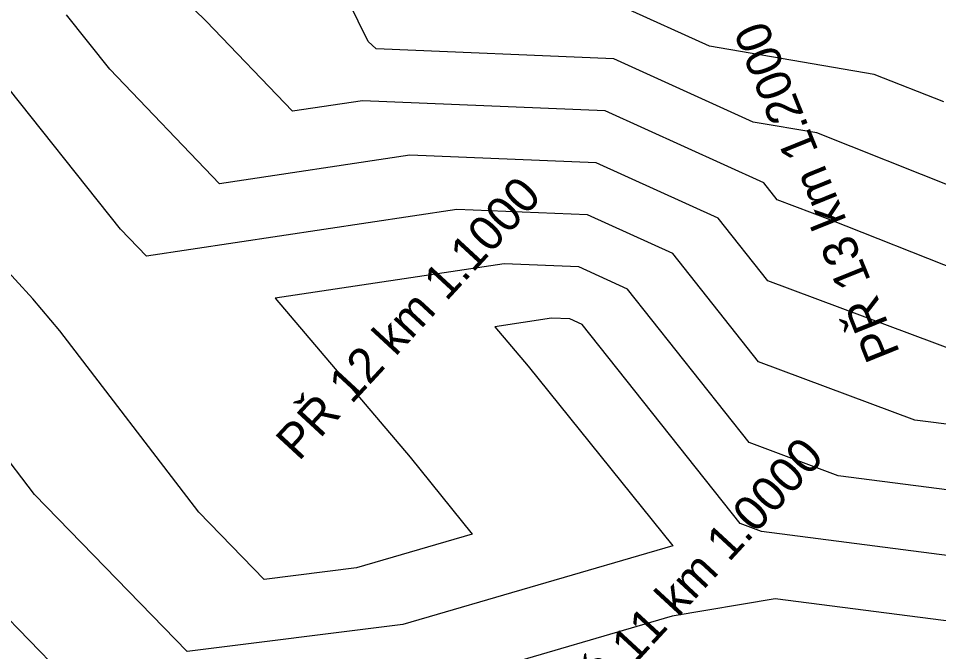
# Model space of a CAD drawing. Extents: x -549394 to -546608, y -1037055 to -1033629.
# Drawn here: x -548577.2 to -548337.9, y -1034297.2 to -1034132.6 of the extents above; entities that cross this region are included whole.
import ezdxf

# ---------------------------------------------------------------- set-up
doc = ezdxf.new("R2010")
doc.units = 0
for name, color, linetype in [('hlavni_vrst', 7, 'Continuous'), ('norm_vrst', 7, 'Continuous'), ('x_popis_pricne_rezy_C21', 7, 'Continuous')]:
    doc.layers.add(name, color=color, linetype=linetype)

msp = doc.modelspace()

# ---------------------------------------------------------------- linework, layer by layer
at = {"layer": 'hlavni_vrst'}
for p, q in [((-548550.64, -1034187.34), (-548582.87, -1034146.92)), ((-548463.15, -1034182.22), (-548543.89, -1034194.39)), ((-548429.21, -1034183.63), (-548463.15, -1034182.22)), ((-548407, -1034193.71), (-548429.21, -1034183.63)), ((-548543.89, -1034194.39), (-548550.64, -1034187.34)), ((-548384.72, -1034221.8), (-548407, -1034193.71)), ((-548344.1, -1034237.02), (-548384.72, -1034221.8)), ((-548328.37, -1034239.03), (-548344.1, -1034237.02))]:
    msp.add_line(p, q, dxfattribs=at)
at = {"layer": 'norm_vrst'}
for p, q in [((-548528.34, -1034133.25), (-548548.15, -1034114.12)), ((-548486.29, -1034138.6), (-548491.42, -1034127.98)), ((-548397.49, -1034139.82), (-548420.1, -1034129.55)), ((-548553.4, -1034145.77), (-548564.7, -1034131.6)), ((-548505.89, -1034156.71), (-548528.34, -1034133.25)), ((-548484.16, -1034140.51), (-548486.29, -1034138.6)), ((-548354.65, -1034147.1), (-548397.49, -1034139.82)), ((-548422.38, -1034143.07), (-548484.16, -1034140.51)), ((-548386.15, -1034159.52), (-548422.38, -1034143.07)), ((-548524.89, -1034175.55), (-548553.4, -1034145.77)), ((-548336.57, -1034154.28), (-548354.65, -1034147.1)), ((-548487.74, -1034153.97), (-548505.89, -1034156.71)), ((-548424.65, -1034156.59), (-548487.74, -1034153.97)), ((-548383.38, -1034175.33), (-548424.65, -1034156.59)), ((-548369.59, -1034162.33), (-548386.15, -1034159.52)), ((-548333.44, -1034176.69), (-548369.59, -1034162.33)), ((-548475.45, -1034168.1), (-548524.89, -1034175.55)), ((-548426.93, -1034170.11), (-548475.45, -1034168.1)), ((-548395.19, -1034184.52), (-548426.93, -1034170.11)), ((-548379.9, -1034179.71), (-548383.38, -1034175.33)), ((-548366.12, -1034184.88), (-548379.9, -1034179.71)), ((-548573.46, -1034205.49), (-548594.36, -1034182.69)), ((-548382.31, -1034200.76), (-548395.19, -1034184.52)), ((-548330.31, -1034199.1), (-548366.12, -1034184.88)), ((-548450.86, -1034196.34), (-548510.41, -1034205.32)), ((-548431.48, -1034197.15), (-548450.86, -1034196.34)), ((-548418.8, -1034202.91), (-548431.48, -1034197.15)), ((-548331.3, -1034219.87), (-548382.31, -1034200.76)), ((-548387.13, -1034242.84), (-548418.8, -1034202.91)), ((-548566.45, -1034213.77), (-548573.46, -1034205.49)), ((-548510.41, -1034205.32), (-548475.29, -1034246.59)), ((-548438.57, -1034210.47), (-548453.34, -1034212.7)), ((-548433.76, -1034210.67), (-548438.57, -1034210.47)), ((-548430.61, -1034212.1), (-548433.76, -1034210.67)), ((-548530.3, -1034260.92), (-548566.45, -1034213.77)), ((-548453.34, -1034212.7), (-548444.63, -1034222.94)), ((-548389.54, -1034263.88), (-548430.61, -1034212.1)), ((-548444.63, -1034222.94), (-548407, -1034269.64)), ((-548572.99, -1034256.36), (-548590.6, -1034233.4)), ((-548364.02, -1034251.5), (-548387.13, -1034242.84)), ((-548475.29, -1034246.59), (-548459.16, -1034266.61)), ((-548330.22, -1034255.82), (-548364.02, -1034251.5)), ((-548533.29, -1034297.15), (-548572.99, -1034256.36)), ((-548553.29, -1034315.9), (-548606.49, -1034261.26)), ((-548513.28, -1034278.39), (-548530.3, -1034260.92)), ((-548383.94, -1034265.98), (-548389.54, -1034263.88)), ((-548459.16, -1034266.61), (-548489.25, -1034275.39)), ((-548332.06, -1034272.62), (-548383.94, -1034265.98)), ((-548407, -1034269.64), (-548477.2, -1034290.13)), ((-548489.25, -1034275.39), (-548513.28, -1034278.39)), ((-548380.36, -1034283.46), (-548407.21, -1034287.96)), ((-548333.91, -1034289.41), (-548380.36, -1034283.46)), ((-548407.21, -1034287.96), (-548465.15, -1034304.87)), ((-548477.2, -1034290.13), (-548533.29, -1034297.15))]:
    msp.add_line(p, q, dxfattribs=at)

# ---------------------------------------------------------------- texts
at = {"layer": 'x_popis_pricne_rezy_C21'}
for s, rotation, p in [('PŘ 13 km 1.2000', 111.9954, (-548347.85, -1034219.47)), ('PŘ 12 km 1.1000', 47.3078, (-548504.29, -1034247.87)), ('PŘ 11 km 1.0000', 47.3078, (-548430.79, -1034315.67))]:
    msp.add_text(s, height=9.0627, rotation=rotation, dxfattribs=at).set_placement(p)

doc.saveas('drawing.dxf')
